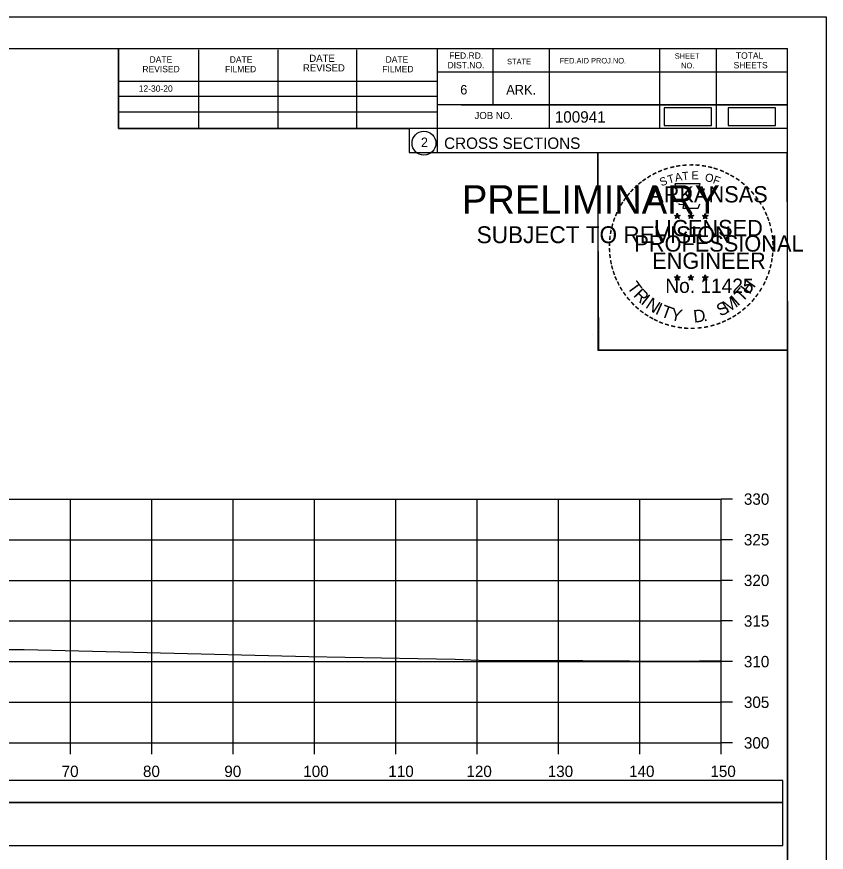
# Model space of a CAD drawing. Extents: x 1370538 to 1372872, y 376220 to 381127.
# Drawn here: x 1371438.7 to 1371538.2, y 380368.9 to 380471.7 of the extents above; entities that cross this region are included whole.
import ezdxf

# ---------------------------------------------------------------- set-up
doc = ezdxf.new("R2010")
doc.units = 0
for name, color, linetype in [('Default', 7, 'Continuous'), ('R_Border Notes', 7, 'Continuous'), ('R_Border PE', 7, 'Continuous'), ('R_Border Prem', 7, 'Continuous'), ('R_Dimension', 7, 'Continuous'), ('R_Grid', 7, 'Continuous'), ('R_No Plot', 7, 'Continuous'), ('T_Detection Zones', 7, 'Continuous'), ('T_Indications', 7, 'Continuous'), ('T_Notes', 7, 'Continuous')]:
    doc.layers.add(name, color=color, linetype=linetype)

msp = doc.modelspace()

# ---------------------------------------------------------------- linework, layer by layer
at = {"layer": 'Default'}
for points in [[(1371518.28, 380458.33), (1371524.11, 380458.33), (1371524.11, 380460.51), (1371518.28, 380460.51)], [(1371526.15, 380458.33), (1371531.98, 380458.33), (1371531.98, 380460.51), (1371526.15, 380460.51)]]:
    msp.add_lwpolyline(points, close=True, dxfattribs=at)
at = {"layer": 'R_Border Notes'}
for p, q in [((1371217.29, 380467.83), (1371533.47, 380467.83)), ((1371451.21, 380457.95), (1371451.21, 380467.83)), ((1371461.07, 380457.95), (1371461.07, 380467.63)), ((1371470.83, 380457.95), (1371470.83, 380467.63)), ((1371480.51, 380457.95), (1371480.51, 380467.63)), ((1371490.37, 380467.83), (1371490.37, 380455.03)), ((1371497.21, 380467.83), (1371497.21, 380460.89)), ((1371504.15, 380467.83), (1371504.15, 380457.95)), ((1371517.73, 380467.83), (1371517.73, 380457.95)), ((1371524.67, 380467.83), (1371524.67, 380457.95)), ((1371533.47, 380262.37), (1371533.47, 380467.83)), ((1371533.47, 380464.89), (1371490.37, 380464.89)), ((1371533.47, 380464.91), (1371533.47, 380464.91)), ((1371451.21, 380463.81), (1371490.37, 380463.81)), ((1371451.21, 380461.95), (1371490.37, 380461.95)), ((1371533.47, 380460.89), (1371490.37, 380460.89)), ((1371493.33, 380460.89), (1371533.47, 380460.89)), ((1371451.21, 380457.95), (1371451.21, 380460.01)), ((1371451.21, 380460.01), (1371490.37, 380460.01)), ((1371533.47, 380457.95), (1371451.21, 380457.95)), ((1371490.37, 380455.03), (1371533.47, 380455.03))]:
    msp.add_line(p, q, dxfattribs=at)
msp.add_circle((1371488.75, 380456.16), 1.47, dxfattribs=at)
at = {"layer": 'R_Border Prem'}
for p, q in [((1371525.29, 380382.37), (1371525.29, 380412.37)), ((1371526.69, 380412.37), (1371525.29, 380412.37)), ((1371526.69, 380407.37), (1371525.29, 380407.37)), ((1371526.69, 380402.37), (1371525.29, 380402.37)), ((1371526.69, 380397.37), (1371525.29, 380397.37)), ((1371526.69, 380392.37), (1371525.29, 380392.37)), ((1371526.69, 380387.37), (1371525.29, 380387.37)), ((1371225.29, 380382.37), (1371525.29, 380382.37)), ((1371445.29, 380380.97), (1371445.29, 380382.37)), ((1371455.29, 380380.97), (1371455.29, 380382.37)), ((1371465.29, 380380.97), (1371465.29, 380382.37)), ((1371475.29, 380380.97), (1371475.29, 380382.37)), ((1371485.29, 380380.97), (1371485.29, 380382.37)), ((1371495.29, 380380.97), (1371495.29, 380382.37)), ((1371505.29, 380380.97), (1371505.29, 380382.37)), ((1371515.29, 380380.97), (1371515.29, 380382.37)), ((1371525.29, 380380.97), (1371525.29, 380382.37)), ((1371526.69, 380382.37), (1371525.29, 380382.37))]:
    msp.add_line(p, q, dxfattribs=at)
at = {"layer": 'R_Dimension'}
msp.add_lwpolyline([(1371435.3, 380393.86), (1371439.58, 380393.88), (1371454.72, 380393.48), (1371474.59, 380393.01), (1371487.99, 380392.74), (1371492.6, 380392.66), (1371495.49, 380392.57), (1371508.3, 380392.52), (1371519.88, 380392.44), (1371522.65, 380392.46), (1371525.29, 380392.48)], dxfattribs=at)
at = {"layer": 'R_Grid'}
for p, q in [((1371225.29, 380412.37), (1371525.29, 380412.37)), ((1371445.29, 380382.37), (1371445.29, 380412.37)), ((1371455.29, 380382.37), (1371455.29, 380412.37)), ((1371465.29, 380382.37), (1371465.29, 380412.37)), ((1371475.29, 380382.37), (1371475.29, 380412.37)), ((1371485.29, 380382.37), (1371485.29, 380412.37)), ((1371495.29, 380382.37), (1371495.29, 380412.37)), ((1371505.29, 380382.37), (1371505.29, 380412.37)), ((1371515.29, 380382.37), (1371515.29, 380412.37)), ((1371525.29, 380382.37), (1371525.29, 380412.37)), ((1371225.29, 380407.37), (1371525.29, 380407.37)), ((1371225.29, 380402.37), (1371525.29, 380402.37)), ((1371225.29, 380397.37), (1371525.29, 380397.37)), ((1371225.29, 380392.37), (1371525.29, 380392.37)), ((1371225.29, 380387.37), (1371525.29, 380387.37)), ((1371225.29, 380382.37), (1371525.29, 380382.37))]:
    msp.add_line(p, q, dxfattribs=at)
at = {"layer": 'R_No Plot'}
for p, q in [((1371204.89, 380471.72), (1371538.22, 380471.72)), ((1371509.5, 380432.57), (1371509.5, 380432.57))]:
    msp.add_line(p, q, dxfattribs=at)
for points in [[(1371204.88, 380471.72), (1371538.22, 380471.72), (1371538.22, 380258.39), (1371204.88, 380258.39)], [(1371451.21, 380467.83), (1371451.21, 380457.95), (1371486.94, 380457.95), (1371486.94, 380455.03), (1371510.14, 380455.03), (1371510.14, 380430.7), (1371533.47, 380430.7), (1371533.47, 380262.37), (1371217.29, 380262.37), (1371217.29, 380467.83)], [(1371510.14, 380455.03), (1371533.35, 380455.03), (1371533.47, 380430.7), (1371510.26, 380430.7)]]:
    msp.add_lwpolyline(points, close=True, dxfattribs=at)
at = {"layer": 'T_Detection Zones'}
for points in [[(1371217.73, 380375.05), (1371532.86, 380375.05), (1371532.86, 380377.76), (1371217.73, 380377.76)], [(1371217.73, 380369.73), (1371532.86, 380369.73), (1371532.86, 380375.05), (1371217.73, 380375.05)]]:
    msp.add_lwpolyline(points, close=True, dxfattribs=at)
at = {"layer": 'T_Indications'}
for p, q in [((1371519.55, 380447.28), (1371519.9, 380447.17)), ((1371519.55, 380447.28), (1371519.8, 380447.24)), ((1371519.55, 380447.28), (1371519.79, 380447.16)), ((1371519.68, 380446.88), (1371519.9, 380447.17)), ((1371519.68, 380446.88), (1371519.81, 380447.12)), ((1371519.68, 380446.88), (1371519.9, 380447.09)), ((1371519.9, 380447.54), (1371519.86, 380447.29)), ((1371519.9, 380447.17), (1371519.9, 380447.54)), ((1371519.9, 380447.54), (1371519.95, 380447.29)), ((1371520.25, 380447.28), (1371519.9, 380447.17)), ((1371520.11, 380446.88), (1371519.9, 380447.17)), ((1371520.11, 380446.88), (1371519.9, 380447.09)), ((1371520.25, 380447.28), (1371519.96, 380447.23)), ((1371520.11, 380446.88), (1371519.98, 380447.17)), ((1371520.25, 380447.28), (1371520.04, 380447.18)), ((1371521.22, 380447.28), (1371521.57, 380447.17)), ((1371521.22, 380447.28), (1371521.47, 380447.24)), ((1371521.22, 380447.28), (1371521.46, 380447.16)), ((1371521.35, 380446.88), (1371521.57, 380447.17)), ((1371521.35, 380446.88), (1371521.48, 380447.12)), ((1371521.35, 380446.88), (1371521.57, 380447.09)), ((1371521.57, 380447.54), (1371521.53, 380447.29)), ((1371521.57, 380447.17), (1371521.57, 380447.54)), ((1371521.57, 380447.54), (1371521.62, 380447.29)), ((1371521.92, 380447.28), (1371521.57, 380447.17)), ((1371521.78, 380446.88), (1371521.57, 380447.17)), ((1371521.78, 380446.88), (1371521.57, 380447.09)), ((1371521.92, 380447.28), (1371521.63, 380447.23)), ((1371521.78, 380446.88), (1371521.65, 380447.17)), ((1371521.92, 380447.28), (1371521.71, 380447.18)), ((1371522.99, 380447.27), (1371523.33, 380447.16)), ((1371522.99, 380447.27), (1371523.24, 380447.23)), ((1371522.99, 380447.27), (1371523.22, 380447.15)), ((1371523.12, 380446.86), (1371523.33, 380447.16)), ((1371523.12, 380446.86), (1371523.24, 380447.11)), ((1371523.12, 380446.86), (1371523.33, 380447.08)), ((1371523.33, 380447.53), (1371523.29, 380447.27)), ((1371523.33, 380447.16), (1371523.33, 380447.53)), ((1371523.33, 380447.53), (1371523.38, 380447.28)), ((1371523.68, 380447.27), (1371523.33, 380447.16)), ((1371523.55, 380446.86), (1371523.33, 380447.16)), ((1371523.55, 380446.86), (1371523.33, 380447.08)), ((1371523.68, 380447.27), (1371523.4, 380447.22)), ((1371523.55, 380446.86), (1371523.41, 380447.15)), ((1371523.68, 380447.27), (1371523.48, 380447.17)), ((1371519.55, 380439.71), (1371519.9, 380439.6)), ((1371519.55, 380439.71), (1371519.8, 380439.67)), ((1371519.55, 380439.71), (1371519.78, 380439.59)), ((1371519.9, 380439.96), (1371519.86, 380439.71)), ((1371519.9, 380439.6), (1371519.9, 380439.96)), ((1371519.9, 380439.96), (1371519.95, 380439.71)), ((1371520.24, 380439.71), (1371519.9, 380439.6)), ((1371520.24, 380439.71), (1371519.96, 380439.66)), ((1371520.24, 380439.71), (1371520.04, 380439.61)), ((1371521.22, 380439.71), (1371521.57, 380439.6)), ((1371521.22, 380439.71), (1371521.47, 380439.67)), ((1371521.22, 380439.71), (1371521.45, 380439.59)), ((1371521.57, 380439.96), (1371521.52, 380439.71)), ((1371521.57, 380439.6), (1371521.57, 380439.96)), ((1371521.57, 380439.96), (1371521.61, 380439.71)), ((1371521.91, 380439.71), (1371521.57, 380439.6)), ((1371521.91, 380439.71), (1371521.63, 380439.66)), ((1371521.91, 380439.71), (1371521.71, 380439.61)), ((1371522.98, 380439.7), (1371523.33, 380439.59)), ((1371522.98, 380439.7), (1371523.24, 380439.66)), ((1371522.98, 380439.7), (1371523.22, 380439.58)), ((1371523.33, 380439.95), (1371523.29, 380439.7)), ((1371523.33, 380439.59), (1371523.33, 380439.95)), ((1371523.33, 380439.95), (1371523.38, 380439.7)), ((1371523.68, 380439.7), (1371523.33, 380439.59)), ((1371523.68, 380439.7), (1371523.39, 380439.65)), ((1371523.68, 380439.7), (1371523.48, 380439.6)), ((1371519.68, 380439.3), (1371519.9, 380439.6)), ((1371519.68, 380439.3), (1371519.81, 380439.55)), ((1371519.68, 380439.3), (1371519.89, 380439.52)), ((1371520.11, 380439.3), (1371519.89, 380439.52)), ((1371520.11, 380439.3), (1371519.9, 380439.6)), ((1371520.11, 380439.3), (1371519.97, 380439.59)), ((1371521.35, 380439.3), (1371521.57, 380439.6)), ((1371521.35, 380439.3), (1371521.48, 380439.55)), ((1371521.35, 380439.3), (1371521.56, 380439.52)), ((1371521.78, 380439.3), (1371521.56, 380439.52)), ((1371521.78, 380439.3), (1371521.57, 380439.6)), ((1371521.78, 380439.3), (1371521.64, 380439.59)), ((1371523.12, 380439.29), (1371523.33, 380439.59)), ((1371523.12, 380439.29), (1371523.24, 380439.54)), ((1371523.12, 380439.29), (1371523.33, 380439.51)), ((1371523.55, 380439.29), (1371523.33, 380439.59)), ((1371523.55, 380439.29), (1371523.33, 380439.51)), ((1371523.55, 380439.29), (1371523.41, 380439.58))]:
    msp.add_line(p, q, dxfattribs=at)
for points in [[(1371519.59, 380451.16), (1371519.86, 380450.33)], [(1371523.1, 380450.24), (1371523.25, 380450.52), (1371522.56, 380450.5), (1371522.71, 380451.16), (1371519.59, 380451.16)], [(1371520.08, 380448.74), (1371520.08, 380448.65), (1371520.65, 380448.63), (1371520.59, 380448.16), (1371522.46, 380448.16), (1371522.66, 380448.7)], [(1371519.9, 380447.54), (1371520.11, 380446.88), (1371519.55, 380447.28), (1371520.25, 380447.28), (1371519.68, 380446.88), (1371519.9, 380447.54)], [(1371521.57, 380447.54), (1371521.78, 380446.88), (1371521.22, 380447.28), (1371521.92, 380447.28), (1371521.35, 380446.88), (1371521.57, 380447.54)], [(1371523.33, 380447.53), (1371523.55, 380446.86), (1371522.99, 380447.27), (1371523.68, 380447.27), (1371523.12, 380446.86), (1371523.33, 380447.53)], [(1371519.9, 380439.96), (1371520.11, 380439.3), (1371519.55, 380439.71), (1371520.24, 380439.71), (1371519.68, 380439.3), (1371519.9, 380439.96)], [(1371521.57, 380439.96), (1371521.78, 380439.3), (1371521.22, 380439.71), (1371521.91, 380439.71), (1371521.35, 380439.3), (1371521.57, 380439.96)], [(1371523.33, 380439.95), (1371523.55, 380439.29), (1371522.98, 380439.7), (1371523.68, 380439.7), (1371523.12, 380439.29), (1371523.33, 380439.95)]]:
    msp.add_lwpolyline(points, dxfattribs=at)
for centre, radius in [((1371519.9, 380447.17), 0.172), ((1371519.9, 380447.17), 0.145), ((1371519.9, 380447.17), 0.116), ((1371519.9, 380447.17), 0.0991), ((1371519.9, 380447.17), 0.0747), ((1371519.9, 380447.17), 0.0495), ((1371519.9, 380447.17), 0.0296), ((1371521.57, 380447.17), 0.172), ((1371521.57, 380447.17), 0.145), ((1371521.57, 380447.17), 0.116), ((1371521.57, 380447.17), 0.0991), ((1371521.57, 380447.17), 0.0747), ((1371521.57, 380447.17), 0.0495), ((1371521.57, 380447.17), 0.0296), ((1371523.33, 380447.16), 0.172), ((1371523.33, 380447.16), 0.145), ((1371523.33, 380447.16), 0.116), ((1371523.33, 380447.16), 0.0991), ((1371523.33, 380447.16), 0.0747), ((1371523.33, 380447.16), 0.0495), ((1371523.33, 380447.16), 0.0296), ((1371519.9, 380439.6), 0.172), ((1371519.9, 380439.6), 0.145), ((1371519.9, 380439.6), 0.116), ((1371519.9, 380439.6), 0.0991), ((1371521.56, 380439.6), 0.172), ((1371521.56, 380439.6), 0.145), ((1371521.56, 380439.6), 0.116), ((1371521.56, 380439.6), 0.0991), ((1371523.33, 380439.59), 0.172), ((1371523.33, 380439.59), 0.145), ((1371523.33, 380439.59), 0.116), ((1371523.33, 380439.59), 0.0991), ((1371519.9, 380439.6), 0.0747), ((1371519.9, 380439.6), 0.0495), ((1371519.9, 380439.6), 0.0296), ((1371521.56, 380439.6), 0.0747), ((1371521.56, 380439.6), 0.0495), ((1371521.56, 380439.6), 0.0296), ((1371523.33, 380439.59), 0.0747), ((1371523.33, 380439.59), 0.0495), ((1371523.33, 380439.59), 0.0296)]:
    msp.add_circle(centre, radius, dxfattribs=at)

# ---------------------------------------------------------------- texts
at = {"layer": 'R_Border Notes'}
for s, height, p in [('DATE', 0.782, (1371455.01, 380466.07)), ('DATE', 0.782, (1371464.87, 380466.07)), ('DATE', 0.879, (1371474.65, 380466.17)), ('DATE', 0.782, (1371484.03, 380466.07)), ('FED.RD.', 0.782, (1371491.85, 380466.55)), ('STATE', 0.684, (1371498.97, 380465.87)), ('FED.AID PROJ.NO.', 0.684, (1371505.43, 380465.97)), ('SHEET', 0.684, (1371519.59, 380466.55)), ('TOTAL', 0.782, (1371527.11, 380466.55)), ('REVISED', 0.782, (1371454.13, 380464.89)), ('FILMED', 0.782, (1371464.29, 380464.89)), ('REVISED', 0.879, (1371473.87, 380464.99)), ('FILMED', 0.782, (1371483.63, 380464.89)), ('DIST.NO.', 0.782, (1371491.65, 380465.37)), ('NO.', 0.684, (1371520.37, 380465.37)), ('SHEETS', 0.782, (1371526.83, 380465.37)), ('6', 1.17, (1371493.21, 380462.15)), ('ARK.', 1.172, (1371498.87, 380462.15)), ('JOB NO.', 0.879, (1371494.97, 380459.13)), ('100941', 1.4, (1371504.84, 380458.69)), ('2', 1.17, (1371488.37, 380455.68)), ('CROSS SECTIONS', 1.4, (1371491.23, 380455.46))]:
    msp.add_text(s, height=height, rotation=360, dxfattribs=at).set_placement(p)
msp.add_text('12-30-20', height=0.78, dxfattribs=at).set_placement((1371453.68, 380462.49))
at = {"layer": 'R_Border PE'}
for s, p in [('330', (1371528.09, 380411.67)), ('325', (1371528.09, 380406.67)), ('320', (1371528.09, 380401.67)), ('315', (1371528.09, 380396.67)), ('310', (1371528.09, 380391.67)), ('305', (1371528.09, 380386.67)), ('300', (1371528.09, 380381.67)), ('70', (1371444.2, 380378.17)), ('80', (1371454.2, 380378.17)), ('90', (1371464.2, 380378.17)), ('100', (1371473.91, 380378.17)), ('110', (1371484.37, 380378.17)), ('120', (1371493.97, 380378.17)), ('130', (1371503.97, 380378.17)), ('140', (1371513.97, 380378.17)), ('150', (1371523.97, 380378.17))]:
    msp.add_text(s, height=1.4, dxfattribs=at).set_placement(p)
at = {"layer": 'T_Indications'}
for s, height, rotation, p in [('-', 1.6, 19.1761, (1371518.34, 380452.29)), ('-', 1.6, 13.6301, (1371519.09, 380452.53)), ('-', 1.6, 10.2193, (1371519.77, 380452.69)), ('-', 1.6, 5.8968, (1371520.5, 380452.8)), ('-', 1.6, 0.1862, (1371521.27, 380452.87)), ('-', 1.6, 357.743, (1371521.99, 380452.86)), ('-', 1.6, 352.1617, (1371522.74, 380452.8)), ('-', 1.6, 347.2049, (1371523.46, 380452.69)), ('-', 1.6, 342.3362, (1371524.09, 380452.54)), ('-', 1.6, 34.0636, (1371516.48, 380451.33)), ('-', 1.6, 28.7918, (1371517.07, 380451.7)), ('-', 1.6, 24.3072, (1371517.71, 380452.02)), ('T', 1, 16.4036, (1371518.86, 380451.17)), ('A', 1, 11.2132, (1371519.69, 380451.42)), ('T', 1, 6.0228, (1371520.54, 380451.59)), ('E', 1, 0.8323, (1371521.64, 380451.7)), ('O', 1, 350.4515, (1371523.25, 380451.49)), ('F', 1, 340.0707, (1371524.2, 380451.26)), ('-', 1.6, 337.8551, (1371524.83, 380452.31)), ('-', 1.6, 334.1211, (1371525.46, 380452.04)), ('-', 1.6, 329.6409, (1371526.04, 380451.76)), ('-', 1.6, 42.9622, (1371514.99, 380450.14)), ('-', 1.6, 38.9507, (1371515.42, 380450.56)), ('-', 1.6, 36.2317, (1371515.9, 380450.94)), ('S', 1, 21.594, (1371517.95, 380450.84)), ('-', 1.6, 325.8627, (1371526.68, 380451.4)), ('-', 1.6, 320.5297, (1371527.29, 380450.97)), ('-', 1.6, 50.6142, (1371514.14, 380449.18)), ('-', 1.6, 48.423, (1371514.54, 380449.66)), ('ARKANSAS', 2, 360, (1371516.45, 380448.87)), ('-', 1.6, 315.5786, (1371527.89, 380450.48)), ('-', 1.6, 309.8797, (1371528.46, 380449.93)), ('-', 1.6, 58.0706, (1371513.4, 380448.08)), ('-', 1.6, 54.2325, (1371513.73, 380448.61)), ('-', 1.6, 306.6522, (1371528.98, 380449.33)), ('-', 1.4, 303.6753, (1371529.47, 380448.76)), ('-', 1.6, 62.8713, (1371513.09, 380447.47)), ('-', 1.6, 299.6684, (1371529.79, 380448.16)), ('-', 1.6, 72.3945, (1371512.61, 380446.23)), ('-', 1.6, 67.7743, (1371512.83, 380446.86)), ('DWB', 0.01, 360, (1371519.89, 380447.17)), ('DWB', 0.01, 360, (1371521.56, 380447.17)), ('DWB', 0.01, 360, (1371523.32, 380447.16)), ('-', 1.6, 294.6628, (1371530.11, 380447.54)), ('-', 1.6, 290.5728, (1371530.37, 380446.97)), ('-', 1.6, 75.461, (1371512.41, 380445.52)), ('LICENSED', 2, 360, (1371517.04, 380444.72)), ('-', 1.6, 285.1233, (1371530.6, 380446.39)), ('-', 1.6, 81.2013, (1371512.28, 380444.8)), ('PROFESSIONAL', 2, 360, (1371514.62, 380442.82)), ('-', 1.6, 280.5493, (1371530.8, 380445.65)), ('-', 1.6, 276.5962, (1371530.96, 380444.88)), ('-', 1.6, 89.0622, (1371512.18, 380443.41)), ('-', 1.6, 85.1863, (1371512.2, 380444.11)), ('-', 1.6, 274.3301, (1371531.02, 380444.16)), ('-', 1.6, 94.1959, (1371512.21, 380442.69)), ('-', 1.6, 269.9407, (1371531.06, 380443.52)), ('-', 1.6, 98.9479, (1371512.29, 380442.02)), ('-', 1.6, 101.7149, (1371512.42, 380441.29)), ('ENGINEER', 2, 360, (1371516.81, 380440.7)), ('-', 1.6, 260.9953, (1371530.97, 380442.2)), ('-', 1.6, 263.5172, (1371531.04, 380442.86)), ('-', 1.6, 105.4578, (1371512.58, 380440.69)), ('-', 1.6, 255.7626, (1371530.86, 380441.53)), ('-', 1.6, 109.0874, (1371512.8, 380440.06)), ('-', 1.6, 114.0643, (1371513.05, 380439.46)), ('-', 1.6, 247.8887, (1371530.45, 380440.13)), ('-', 1.6, 252.8681, (1371530.68, 380440.81)), ('-', 1.6, 115.7289, (1371513.36, 380438.85)), ('T', 1.54, 306.0406, (1371513.66, 380438.44)), ('No. 11425', 1.757, 360, (1371518.43, 380437.74)), ('DWB', 0.01, 360, (1371519.88, 380439.59)), ('DWB', 0.01, 360, (1371521.55, 380439.6)), ('DWB', 0.01, 360, (1371523.32, 380439.59)), ('H', 1.54, 54.6088, (1371528.78, 380437.47)), ('-', 1.6, 244.6197, (1371530.19, 380439.5)), ('-', 1.6, 120.4471, (1371513.71, 380438.26)), ('-', 1.6, 125.8934, (1371514.12, 380437.7)), ('R', 1.54, 314.005, (1371514.42, 380437.39)), ('T', 1.54, 46.6444, (1371527.89, 380436.53)), ('-', 1.6, 233.8452, (1371529.4, 380438.1)), ('-', 1.6, 239.0712, (1371529.8, 380438.75)), ('-', 1.6, 130.7181, (1371514.58, 380437.15)), ('-', 1.6, 134.2238, (1371515.1, 380436.6)), ('I', 1.54, 321.9694, (1371515.32, 380436.46)), ('N', 1.54, 326.5002, (1371515.89, 380435.99)), ('S', 1.54, 26.9312, (1371525.2, 380434.8)), ('M', 1.54, 32.6563, (1371526.04, 380435.21)), ('I', 1.54, 42.1136, (1371527.32, 380436.05)), ('-', 1.6, 231.2538, (1371528.97, 380437.53)), ('-', 1.6, 138.9338, (1371515.62, 380436.14)), ('-', 1.6, 144.6463, (1371516.18, 380435.73)), ('I', 1.54, 335.3603, (1371517.09, 380435.2)), ('T', 1.54, 339.8912, (1371517.76, 380434.87)), ('Y', 1.54, 347.8556, (1371518.97, 380434.43)), ('D', 1.54, 6.3969, (1371521.96, 380434.07)), ('-', 1.6, 221.0851, (1371527.96, 380436.46)), ('-', 1.6, 225.7653, (1371528.49, 380436.97)), ('-', 1.6, 148.0898, (1371516.74, 380435.36)), ('-', 1.6, 151.5704, (1371517.32, 380435.04)), ('-', 1.6, 154.6002, (1371517.84, 380434.79)), ('-', 1.6, 207.3568, (1371526.32, 380435.25)), ('-', 1.6, 212.2491, (1371526.88, 380435.6)), ('-', 1.6, 215.7363, (1371527.42, 380435.99)), ('-', 1.6, 158.5612, (1371518.46, 380434.53)), ('-', 1.6, 162.7983, (1371519.15, 380434.32)), ('-', 1.6, 167.5555, (1371519.87, 380434.16)), ('-', 1.6, 173.1155, (1371520.64, 380434.05)), ('-', 1.6, 185.8167, (1371522.94, 380434.09)), ('-', 1.6, 191.2858, (1371523.67, 380434.22)), ('.', 1.54, 13.7642, (1371523.15, 380434.2)), ('-', 1.6, 195.4743, (1371524.4, 380434.42)), ('-', 1.6, 200.7184, (1371525.08, 380434.66)), ('-', 1.6, 204.2516, (1371525.7, 380434.94)), ('-', 1.6, 176.5183, (1371521.39, 380433.99)), ('-', 1.6, 181.5918, (1371522.13, 380434.01))]:
    msp.add_text(s, height=height, rotation=rotation, dxfattribs=at).set_placement(p)
at = {"layer": 'T_Notes'}
for s, height, p in [('PRELIMINARY', 3.5, (1371493.42, 380447.49)), ('DWB', 0.01, (1371494.16, 380449.34)), ('SUBJECT TO REVISION', 2.0751, (1371495.23, 380443.86))]:
    msp.add_text(s, height=height, rotation=360, dxfattribs=at).set_placement(p)

doc.saveas('drawing.dxf')
